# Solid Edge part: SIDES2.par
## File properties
Author: Andrea Rangi V
Template: Ansi Metric part.par
Last saved by: Andrea Rangi V
Revision: 5
Application: Solid Edge
Accuracy: 0.990
Username: Andrea Rangi V
Face Style: Model Default
Coef. of Thermal Exp: 0.0
Thermal Conductivity: 0.0
Specific Heat: 0.0
Modulus of Elasticity: 0.0
Poisson's Ratio: 0.0
Yield Stress: 0.0
Ultimate Stress: 0.0
Elongation: 0.0
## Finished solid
Body 1: solid body, 83 faces, 242 edges, 160 vertices.
  Faces by surface: plane 80, cylinder 3
  Edges by curve: line 236, circle 6
Bounding box of the edges (mm): 270.000 x 3.000 x 291.000, from (-178.5604, 0, -154.8963) to (91.4396, 3, 136.1037).
Cylindrical faces by radius (mm): R15.9637 x1, R39.0606 x1, R216.9693 x1
Planar faces by outward normal: +x 20, +y 1, +z 19, -x 19, -y 1, -z 20
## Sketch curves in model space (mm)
line (61.4396, 0, 136.1037) -> (91.4396, 0, 136.1037)
line (51.4396, 0, -154.8963) -> (61.4396, 0, -154.8963)
line (-138.5604, 0, -154.8963) -> (-128.5604, 0, -154.8963)
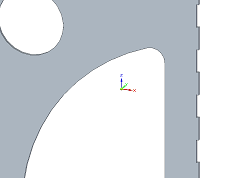
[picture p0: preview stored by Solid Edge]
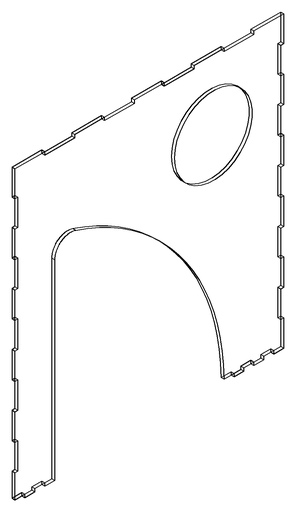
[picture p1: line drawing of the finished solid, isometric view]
